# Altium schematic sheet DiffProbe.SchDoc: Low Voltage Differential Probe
size A3; Date: 19-SEP-2023; Author: JFOSTER; DrawnBy: JFOSTER; Engineer: JFOSTER; Revision: A; SheetNumber: 1; SheetTotal: 1
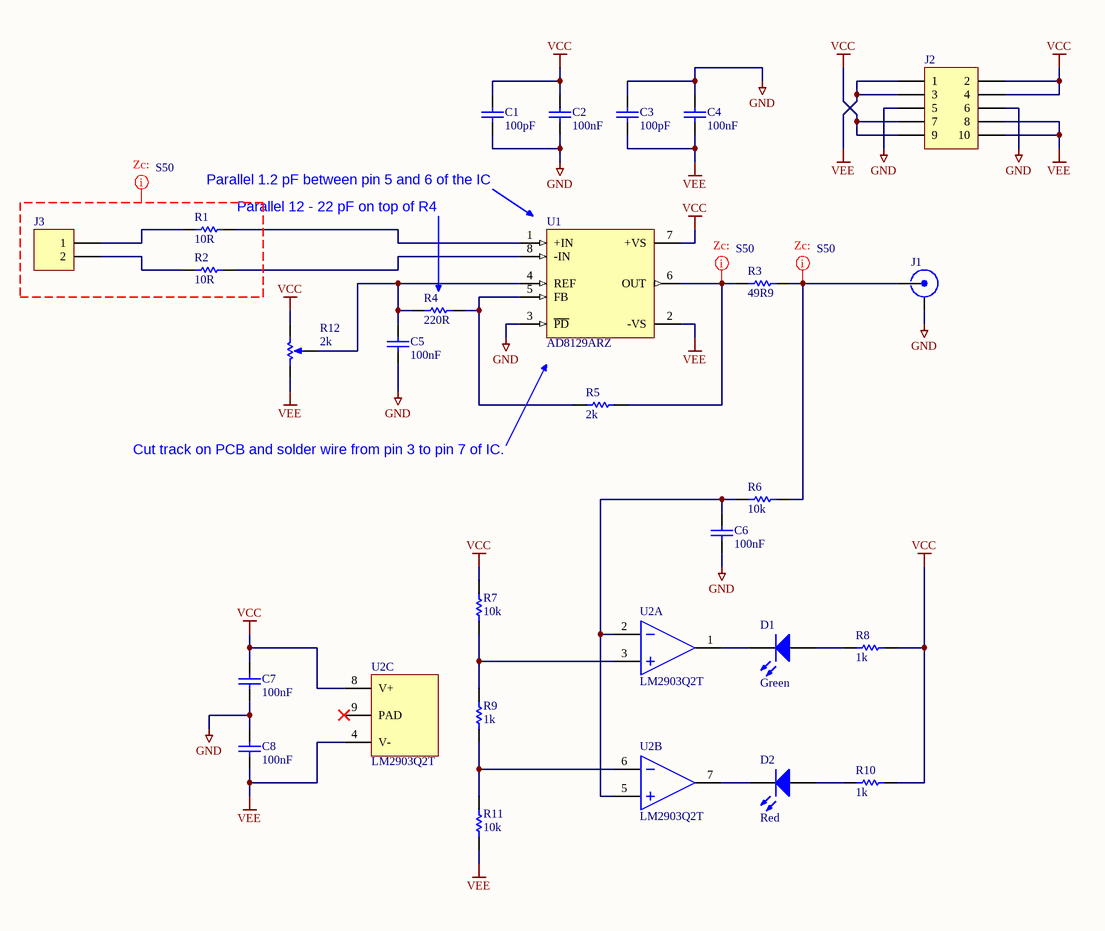
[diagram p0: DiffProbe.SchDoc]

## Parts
C1  100pF  [Cap,SMD,0402]
C2  100nF  [Cap,SMD,0402]
C3  100pF  [Cap,SMD,0402]
C4  100nF  [Cap,SMD,0402]
C5  100nF  [Cap,SMD,0402]
C6  100nF  [Cap,SMD,0402]
C7  100nF  [Cap,SMD,0402]
C8  100nF  [Cap,SMD,0402]
D1  Green  [LED,0603]
D2  Red  [LED,0603]
J1  CON-SMA-EDGE-S  [CONN,SMA,50OHM,EDGE]  (value not drawn)
J2  Term,Header,5x2 Pin,1.27mm,SMD  [TERM,HEADER,5X2PIN,P1.27,SMD]  (value not drawn)
J3  Term,Header,2 Pin,Top,2.54mm  [Term,Header,2Pin,2.54mm]  (value not drawn)
R1  10R  [RES,0402]
R2  10R  [RES,0402]
R3  49R9  [RES,0402]
R4  220R  [RES,0402]
R5  2k  [RES,0402]
R6  10k  [RES,0402]
R7  10k  [RES,0402]
R8  1k  [RES,0402]
R9  1k  [RES,0402]
R10  1k  [RES,0402]
R11  10k  [RES,0402]
R12  2k  [Res,Trim,5T,Top-Adj,SMD]
U1  AD8129ARZ  [IC,SOIC-8,1.27mm,W3.9]
U2  LM2903Q2T  [IC,DFN-8,P0.5,PAD]  (parts A,B,C of 3)

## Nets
GND: C1.1 C2.1 C3.2 C4.2 C5.1 C6.1 C7.1 C8.2 J1.2(GND) J2.5 J2.6 U1.3(~{PD})
VCC: C1.2 C2.2 C7.2 J2.2 J2.4 J2.7 J2.9 R7.2 R8.1 R10.1 R12.3(TOP) U1.7(+VS) U2.8(V+)
VEE: C3.1 C4.1 C8.1 J2.1 J2.3 J2.8 J2.10 R11.1 R12.1(BOT) U1.2(-VS) U2.4(V-)
NetC5_2: C5.2 R4.1 R12.2(TAP) U1.4(REF)
NetC6_2: C6.2 R6.2 U2.2(IN1-) U2.5(IN2+)
NetD1_1: D1.1(A) R8.2
NetD1_2: D1.2(K) U2.1(OUT1)
NetD2_1: D2.1(A) R10.2
NetD2_2: D2.2(K) U2.7(OUT2)
NetJ1_1: J1.1(RF) R3.2 R6.1
NetJ3_1: J3.1 R1.1
NetJ3_2: J3.2 R2.1
NetR1_2: R1.2 U1.1(+IN)
NetR2_2: R2.2 U1.8(-IN)
NetR3_1: R3.1 R5.2 U1.6(OUT)
NetR4_2: R4.2 R5.1 U1.5(FB)
NetR7_1: R7.1 R9.2 U2.3(IN1+)
NetR9_1: R9.1 R11.2 U2.6(IN2-)

Not connected (* = marked no-connect by the designer): U2 9(PAD)*

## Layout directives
net class S50: (no net found under the mark), NetJ1_1, NetR3_1

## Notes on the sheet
- Parallel 1.2 pF between pin 5 and 6 of the IC
- (near R1) Parallel 12 - 22 pF on top of R4
- Cut track on PCB and solder wire from pin 3 to pin 7 of IC.

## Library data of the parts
C1 C3 = CAP,Cer,100pF,50VDC,C0G/NP0,0402: 100pF ±5% 50V Ceramic Capacitor C0G, NP0 0402 (1005 Metric); Vendor Part Number: 490-10669-1-ND; Manufacturer: Murata Electronics; Manufacturer Part Number: GCM1555C1H101JA16D; Vendor: Digikey
C2 C4-C8 = CAP,Cer,100nF,25VDC,X7R,0402: 0.1µF ±10% 25V Ceramic Capacitor X7R 0402 (1005 Metric); Vendor Part Number: 490-14603-1-ND; Manufacturer: Murata Electronics; Manufacturer Part Number: GRM155R71E104KE14J; Vendor: Digikey
D1 = LED,Green,SMD,0603: Green 530nm LED Indication - Discrete 3V 0603 (1608 Metric); Manufacturer: Stanley Electric Co; Manufacturer Part Number: THG1111C-0005-TR; Vendor Part Number: 404-1286-1-ND; Vendor: Digikey
D2 = LED,Red,SMD,0603: Red 633nm LED Indication - Discrete 2V 0603 (1608 Metric); Manufacturer: Lite-On Inc.; Manufacturer Part Number: LS Q976-NR-1; Vendor Part Number: 475-2512-1-ND; Vendor: Digikey
J1 = Conn,RF,SMA,Fem,50R,Edge,SMD: SMA Connector Jack, Female Socket Board Edge, End Launch Solder; Manufacturer: RF Solutions; Vendor Part Number: CON-SMA-EDGE-S-ND; Vendor: DigiKey
J2 = Term,Header,5x2 Pin,1.27mm,SMD: Connector Header Surface Mount 10 position 0.050" (1.27mm); Vendor Part Number: 609-3695-1-ND; Manufacturer: Amphenol ICC (FCI); Manufacturer Part Number: 20021121-00010C4LF; Vendor: Digikey
J3 = Term,Header,2 Pin,Top,2.54mm: CONN HEADER VERT 2POS 2.54MM
R1 R2 = RES,10R,1%,0.063W,0402: 10 Ohms ±1% 0.063W, 1/16W Chip Resistor 0402 (1005 Metric) Automotive AEC-Q200 Thick Film; Manufacturer: Panasonic Electronic Components; Manufacturer Part Number: ERJ-2RKF10R0X; Vendor Part Number: P10.0LCT-ND; Vendor: Digikey
R3 = RES,49R9,1%,0.063W,0402: 49.9 Ohms ±1% 0.063W, 1/16W Chip Resistor 0402 (1005 Metric) Moisture Resistant Thick Film; Manufacturer: Yageo; Manufacturer Part Number: RC0402FR-0749R9L; Vendor Part Number: 311-49.9LRCT-ND; Vendor: Digikey
R4 = RES,220R,1%,0.063W,0402: 220 Ohms ±1% 0.063W, 1/16W Chip Resistor 0402 (1005 Metric) Moisture Resistant Thick Film; Manufacturer: Yageo; Manufacturer Part Number: RC0402FR-07220RL; Vendor Part Number: 311-220LRCT-ND; Vendor: Digikey
R5 = RES,2k,1%,0.063W,0402: 2 kOhms ±1% 0.063W, 1/16W Chip Resistor 0402 (1005 Metric) Automotive AEC-Q200 Thick Film; Vendor Part Number: RMCF0402FT2K00CT-ND; Manufacturer: Stackpole Electronics Inc; Manufacturer Part Number: RMCF0402FT2K00; Vendor: DIgikey
R6 R7 R11 = RES,10k,5%,0.063W,0402: 10 kOhms ±5% 0.063W, 1/16W Chip Resistor 0402 (1005 Metric) Automotive AEC-Q200 Thick Film; Vendor Part Number: RMCF0402JT10K0CT-ND; Manufacturer: Stackpole Electronics Inc; Manufacturer Part Number: RMCF0402JT10K0; Vendor: DIgikey
R8-R10 = RES,1k,5%,0.063W,0402: 1 kOhms ±5% 0.063W, 1/16W Chip Resistor 0402 (1005 Metric) Automotive AEC-Q200 Thick Film; Vendor Part Number: RMCF0402JT1K00CT-ND; Manufacturer: Stackpole Electronics Inc; Manufacturer Part Number: RMCF0402JT1K00; Vendor: DIgikey
R12 = RES,Trim,5T,2k,0.75W,Top-Adj,SMD: 0.25W, 1/4W J Lead Surface Mount Trimmer Potentiometer Cermet Turn Top Adjustment; Manufacturer Part Number: 3214W-202ECT-ND; Vendor Part Number: 3214W-1-202E; Manufacturer: Bourns Inc.; Vendor: Digikey
U1 = AD8129ARZ: Differential Amplifier 1 Circuit 8-SOIC; Manufacturer: Analog Devices Inc.; Vendor Part Number: 505-AD8129ARZ-ND; Vendor: DigiKey
U2 = LM2903Q2T: Comparator Differential CMOS, DTL, ECL, TTL 8-DFN (2x2); Manufacturer: STMicroelectronics; Vendor Part Number: 497-13503-1-ND; Vendor: Digikey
